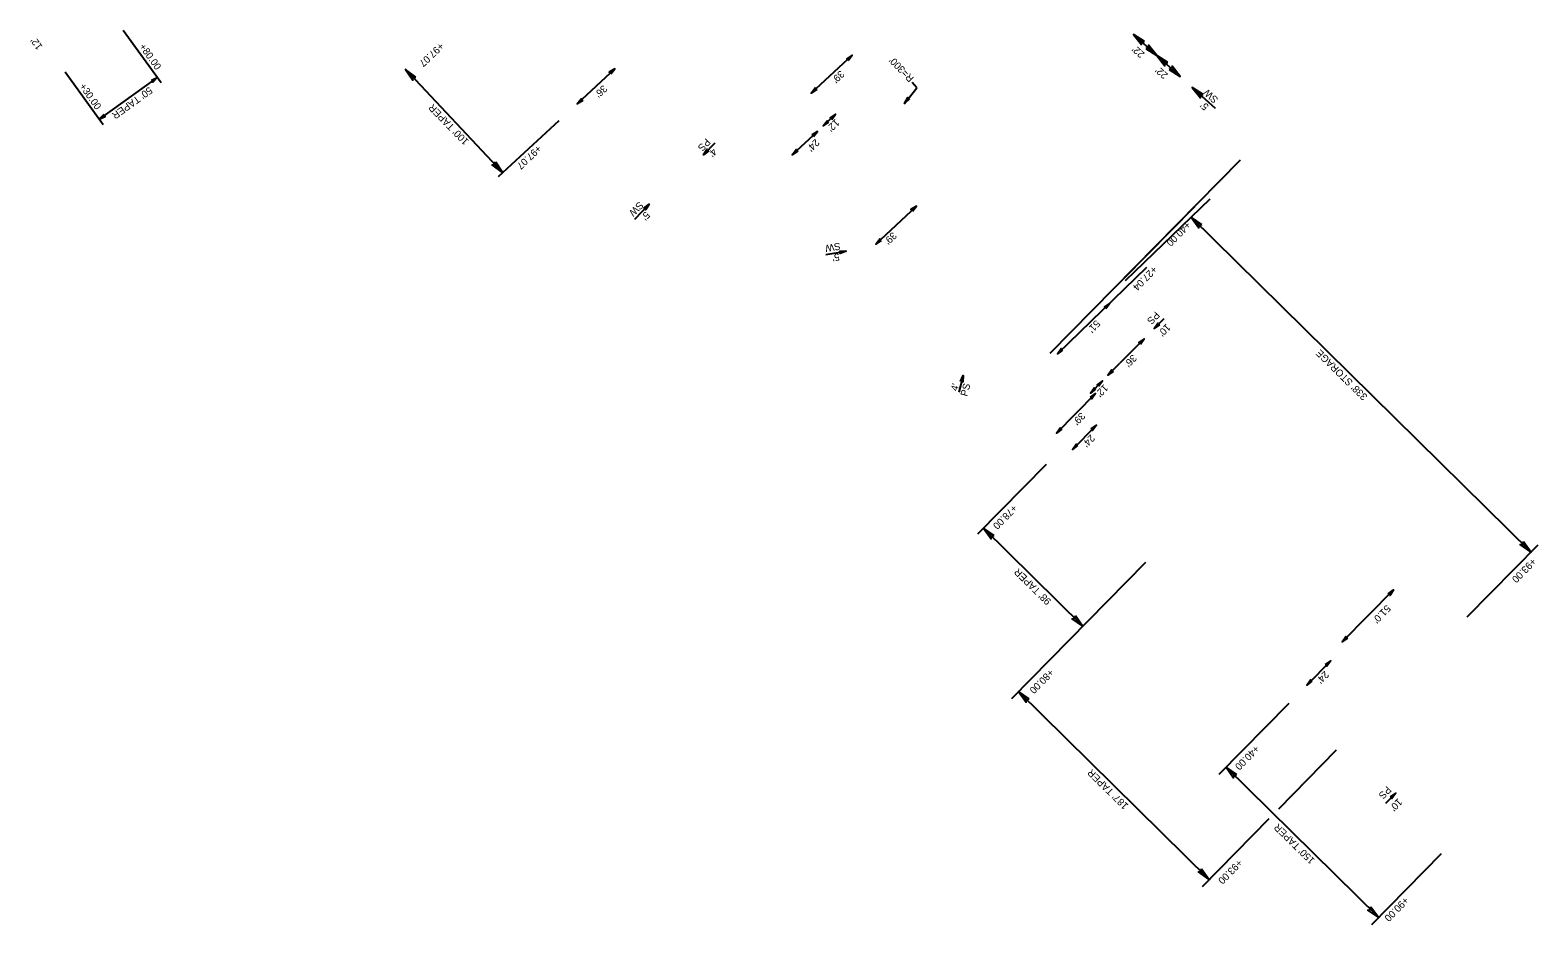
# Model space of a CAD drawing. Extents: x 1262642 to 1268358, y 767825 to 773481.
# Drawn here: x 1263063 to 1264118, y 768451 to 769077 of the extents above; entities that cross this region are included whole.
import ezdxf

# ---------------------------------------------------------------- set-up
doc = ezdxf.new("R2010")
doc.units = 0
for name, color, linetype in [('Prop Dimension', 7, 'Continuous'), ('Prop Dimension Text', 7, 'Continuous'), ('Prop Terminator CELL', 7, 'Continuous')]:
    doc.layers.add(name, color=color, linetype=linetype)

msp = doc.modelspace()

# ---------------------------------------------------------------- linework, layer by layer
at = {"layer": 'Prop Dimension'}
for p, q in [((1263675.2, 769025.9), (1263683.8, 769036.9)), ((1263683.8, 769036.9), (1263680.5, 769040.6)), ((1263777.1, 768851.2), (1263910.3, 768986.4)), ((1263829.7, 768901.9), (1263889.1, 768959.2)), ((1263878, 768953.6), (1263828.4, 768903.2)), ((1264113.7, 768712), (1263875.8, 768946.4)), ((1263817.5, 768835.7), (1263825.9, 768844.2)), ((1263716.3, 768835.5), (1263713.2, 768823.9)), ((1263805.2, 768823.2), (1263813.7, 768831.7)), ((1263781.5, 768795.2), (1263808.9, 768823)), ((1263792.6, 768783.8), (1263809.4, 768800.9)), ((1263774.3, 768773.3), (1263726.3, 768724.6)), ((1263800, 768660.2), (1263730.4, 768728.8)), ((1264118.4, 768716.8), (1264068.8, 768666.4)), ((1263843.9, 768704.7), (1263750, 768609.4)), ((1264017.3, 768685.5), (1263981.5, 768649.1)), ((1263888.4, 768483), (1263755, 768614.5)), ((1263944, 768606.1), (1263895.1, 768556.5)), ((1263977.3, 768573.3), (1263936.9, 768532.2)), ((1264007, 768456.3), (1263900.2, 768561.5)), ((1263930.2, 768525.4), (1263883.4, 768477.9)), ((1264050.8, 768500.8), (1264001.9, 768451.2))]:
    msp.add_line(p, q, dxfattribs=at)
for points in [[(1263853.5, 768871.1), (1263849.8, 768868.4), (1263852.4, 768872.2), (1263852.6, 768871.2)], [(1263985.2, 768651.8), (1263981.5, 768649.1), (1263984.1, 768652.9), (1263984.2, 768652)], [(1263960.3, 768621.6), (1263956.6, 768618.9), (1263959.2, 768622.7), (1263959.3, 768621.7)]]:
    msp.add_lwpolyline(points, close=True, dxfattribs=at)
at = {"layer": 'Prop Dimension Text'}
for p, q in [((1263128.3, 769077.1), (1263154.8, 769040.5)), ((1263868, 769044.7), (1263835.3, 769074.2)), ((1263638.5, 769059.6), (1263609.9, 769033.1)), ((1263087.8, 769047.9), (1263114.2, 769011.2)), ((1263152.2, 769044.1), (1263111.6, 769014.8)), ((1263393.8, 768977.5), (1263325.9, 769049.8)), ((1263472.4, 769050.2), (1263446.1, 769025.5)), ((1263892.9, 769022.3), (1263876.5, 769037)), ((1263433.2, 769013.6), (1263390.7, 768974.6)), ((1263618.2, 769010.1), (1263626.9, 769018.4)), ((1263614.2, 769006.3), (1263596.6, 768990)), ((1263542.4, 768998.1), (1263534.4, 768990)), ((1263486.3, 768945), (1263496.4, 768955.3)), ((1263655.1, 768927.4), (1263683.5, 768954.1)), ((1263620.1, 768920.1), (1263634.3, 768922.6)), ((1263844.6, 768911.1), (1263782.1, 768850.7)), ((1263849.8, 768868.4), (1263856.8, 768875.5)), ((1263842.8, 768861.3), (1263825.9, 768844.2)), ((1263805.2, 768823.2), (1263813.7, 768831.7)), ((1263973.4, 768636), (1263956.6, 768618.9)), ((1264011.9, 768536.3), (1264018.9, 768543.4))]:
    msp.add_line(p, q, dxfattribs=at)
for points in [[(1263843.1, 769069.3), (1263835.3, 769074.2), (1263841, 769067), (1263841.2, 769068.9)], [(1263844, 769064.4), (1263851.7, 769059.5), (1263846, 769066.7), (1263845.8, 769064.8)], [(1263635.7, 769056), (1263638.5, 769059.6), (1263634.7, 769057.1), (1263635.6, 769056.9)], [(1263859.4, 769054.6), (1263851.7, 769059.5), (1263857.3, 769052.2), (1263857.5, 769054.2)], [(1263860.3, 769049.6), (1263868, 769044.7), (1263862.4, 769052), (1263862.1, 769050)], [(1263148.1, 769042.1), (1263152.2, 769044.1), (1263149, 769040.8), (1263149, 769041.8)], [(1263333.2, 769044.3), (1263325.9, 769049.7), (1263331, 769042.1), (1263331.3, 769044)], [(1263469.6, 769046.5), (1263472.4, 769050.2), (1263468.5, 769047.7), (1263469.5, 769047.5)], [(1263613.7, 769035.6), (1263609.9, 769033.1), (1263612.7, 769036.8), (1263612.8, 769035.8)], [(1263884.2, 769032.1), (1263876.5, 769037), (1263882.2, 769029.8), (1263882.4, 769031.7)], [(1263449.9, 769028), (1263446.1, 769025.5), (1263448.9, 769029.2), (1263449, 769028.2)], [(1263114.8, 769018.1), (1263111.6, 769014.8), (1263115.8, 769016.8), (1263114.8, 769017.2)], [(1263622, 769012.7), (1263618.2, 769010.1), (1263621, 769013.8), (1263621.1, 769012.8)], [(1263624.2, 769014.7), (1263626.9, 769018.4), (1263623.1, 769015.9), (1263624.1, 769015.7)], [(1263611.5, 769002.7), (1263614.2, 769006.3), (1263610.4, 769003.8), (1263611.3, 769003.6)], [(1263538.1, 768992.7), (1263534.4, 768990), (1263537, 768993.8), (1263537.2, 768992.8)], [(1263600.4, 768992.5), (1263596.6, 768990), (1263599.4, 768993.7), (1263599.5, 768992.7)], [(1263388.8, 768985.1), (1263393.8, 768977.5), (1263386.5, 768983), (1263388.4, 768983.3)], [(1263492.7, 768952.6), (1263496.4, 768955.3), (1263493.9, 768951.5), (1263493.7, 768952.4)], [(1263680.7, 768950.5), (1263683.5, 768954.1), (1263679.6, 768951.7), (1263680.6, 768951.5)], [(1263883.3, 768941.2), (1263875.8, 768946.4), (1263881.2, 768938.9), (1263881.5, 768940.8)], [(1263658.9, 768929.9), (1263655.1, 768927.4), (1263657.9, 768931.1), (1263658, 768930.1)], [(1263629.7, 768922.6), (1263634.3, 768922.6), (1263630, 768921), (1263630.4, 768921.9)], [(1263816.1, 768882.4), (1263818.8, 768886.1), (1263815, 768883.6), (1263815.9, 768883.4)], [(1263840.2, 768857.5), (1263842.8, 768861.3), (1263839.1, 768858.6), (1263840, 768858.5)], [(1263785.8, 768853.3), (1263782.1, 768850.7), (1263784.8, 768854.4), (1263784.9, 768853.5)], [(1263811, 768828), (1263813.6, 768831.7), (1263809.9, 768829.1), (1263810.9, 768828.9)], [(1263821.2, 768838.3), (1263817.5, 768835.7), (1263820.1, 768839.5), (1263820.3, 768838.5)], [(1263808.9, 768825.9), (1263805.2, 768823.2), (1263807.8, 768827), (1263808, 768826)], [(1263805.2, 768820.3), (1263808.9, 768823), (1263806.3, 768819.2), (1263806.2, 768820.1)], [(1263785.2, 768797.9), (1263781.5, 768795.2), (1263784.1, 768799), (1263784.3, 768798)], [(1263805.7, 768798.3), (1263809.4, 768800.9), (1263806.8, 768797.1), (1263806.7, 768798.1)], [(1263796.3, 768786.5), (1263792.6, 768783.8), (1263795.2, 768787.6), (1263795.3, 768786.7)], [(1263737.9, 768723.6), (1263730.4, 768728.8), (1263735.7, 768721.3), (1263736, 768723.2)], [(1264108.4, 768719.4), (1264113.7, 768712), (1264106.1, 768717.2), (1264108.1, 768717.5)], [(1264013.6, 768682.8), (1264017.3, 768685.5), (1264014.7, 768681.7), (1264014.5, 768682.6)], [(1263794.7, 768667.6), (1263800, 768660.2), (1263792.5, 768665.4), (1263794.4, 768665.7)], [(1263969.7, 768633.3), (1263973.4, 768636), (1263970.8, 768632.2), (1263970.7, 768633.2)], [(1263762.5, 768609.3), (1263755, 768614.5), (1263760.3, 768607), (1263760.6, 768608.9)], [(1263907.7, 768556.3), (1263900.2, 768561.5), (1263905.5, 768554), (1263905.8, 768556)], [(1264015.2, 768540.8), (1264018.9, 768543.4), (1264016.3, 768539.6), (1264016.2, 768540.6)], [(1263883.1, 768490.4), (1263888.4, 768483), (1263880.8, 768488.2), (1263882.8, 768488.5)], [(1264001.6, 768463.7), (1264007, 768456.3), (1263999.4, 768461.5), (1264001.3, 768461.9)]]:
    msp.add_lwpolyline(points, close=True, dxfattribs=at)
at = {"layer": 'Prop Terminator CELL'}
for points in [[(1263678.6, 769029), (1263675.2, 769025.9), (1263677.4, 769030), (1263677.7, 769029)], [(1263714.4, 768831.4), (1263716.3, 768835.5), (1263715.9, 768831), (1263715.3, 768831.7)]]:
    msp.add_lwpolyline(points, close=True, dxfattribs=at)

# ---------------------------------------------------------------- texts
at = {"layer": 'Prop Dimension'}
for s, rotation, p in [("12'", 125.8167, (1263072.2, 769065.6)), ("R=300'", 134.2575, (1263682.1, 769043.8)), ("50' TAPER", 215.8167, (1263146.5, 769037.8)), ("100' TAPER", 134.2575, (1263370.6, 768999.7))]:
    msp.add_text(s, height=5, rotation=rotation, dxfattribs=at).set_placement(p)
at = {"layer": 'Prop Dimension Text'}
for s, rotation, p in [('+80.00', 305.3831, (1263139.3, 769065.6)), ('+97.07', 223.3665, (1263350, 769068.8)), ("22'", 138.1912, (1263843.6, 769060.9)), ("39'", 223.989, (1263630.2, 769049.3)), ("22'", 138.1912, (1263859.9, 769046.2)), ('+30.00', 305.3831, (1263097.4, 769037.8)), ("36'", 223.3665, (1263464.2, 769039.1)), ('SW', 138.1912, (1263895.1, 769029.2)), ("5'", 138.1912, (1263888.5, 769024.2)), ("12'", 223.989, (1263626.8, 769015.3)), ('PS', 225.6948, (1263536.3, 769001.8)), ("24'", 223.989, (1263612.8, 769001.4)), ('+97.07', 223.3665, (1263418.3, 768997.1)), ("4'", 225.6948, (1263540.9, 768994.9)), ('SW', 225.6948, (1263489.4, 768957.6)), ("5'", 225.6948, (1263494, 768950.7)), ("39'", 223.989, (1263666.8, 768936.3)), ('+40.00', 225.4239, (1263872.5, 768943.6)), ('SW', 190.0198, (1263629.9, 768928.6)), ("5'", 190.0198, (1263629.2, 768921.1)), ('+27.04', 225.6948, (1263849, 768912.6)), ("51'", 225.6948, (1263809.1, 768874.7)), ('PS', 225.6948, (1263850.7, 768880.7)), ("10'", 225.6948, (1263858.4, 768872.1)), ("338' STORAGE", 135.4239, (1263999.5, 768821.2)), ("36'", 225.6948, (1263834.7, 768850.6)), ("4'", 75.0169, (1263712.2, 768824.3)), ('PS', 75.0169, (1263719, 768820.6)), ("12'", 225.6948, (1263814.7, 768829.7)), ("39'", 225.6948, (1263798.6, 768810.1)), ("24'", 225.6948, (1263805.4, 768794.6)), ('+78.00', 225.4239, (1263751.1, 768745.6)), ('+93.00', 225.4239, (1264114.3, 768708.2)), ("98' TAPER", 135.4239, (1263778.2, 768678)), ("51.0'", 225.6948, (1264012.4, 768675.4)), ('+80.00', 225.4239, (1263776.7, 768630.6)), ("24'", 225.6948, (1263969.2, 768629.2)), ('+40.00', 225.4239, (1263920.5, 768577.2)), ("187' TAPER", 135.4239, (1263832.2, 768534.9)), ('PS', 225.6948, (1264012.8, 768548.6)), ("10'", 225.6948, (1264020.5, 768540)), ("150' TAPER", 135.4239, (1263962.7, 768496.7)), ('+93.00', 225.4239, (1263908.7, 768497.4)), ('+90.00', 225.4239, (1264025.1, 768471.2))]:
    msp.add_text(s, height=5, rotation=rotation, dxfattribs=at).set_placement(p)

doc.saveas('drawing.dxf')
